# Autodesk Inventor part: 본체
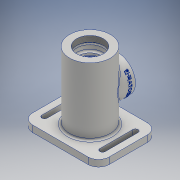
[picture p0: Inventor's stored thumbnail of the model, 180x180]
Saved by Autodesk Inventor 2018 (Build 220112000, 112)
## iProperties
Created: 2021-07
Part Number: 본체
Material: 알루미늄 6061
Document SubType Name: Modeling
Designer: 1class9
Density: 2.7 g/cm^3
Appearance: 알루미늄 - 평지
Mass: 736.573 g
Surface Area: 646.785 cm^2
Volume: 272.805 cm^3
Author: 1class9
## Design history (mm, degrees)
sketch "스케치1"
  geometry: C1 r 31 at (0, 0); 1 further point
  constraints: 1 centre point, 1 coincident
  dimensions: "d0" = 62 diameter of C1
extrude "돌출1" new body sketch "스케치1" stored distance "d1" = 102; taper "d2" = 0 deg
sketch "스케치3"
  geometry: L1 (31, -51)-(-31, -51) reference; L2 (-31, -51)-(-31, 51) reference; L3 (-31, 51)-(31, 51) reference; L4 (31, 51)-(31, -51) reference; L5 (42, -5)-(0, -5); L6 (0, -5)-(0, -32); L7 (0, -32)-(42, -32); L8 (42, -32)-(42, -5); 2 further points
  constraints: 8 end point, 2 parallel, 1 horizontal, 1 midpoint, 1 perpendicular, 1 vertical alignment
  dimensions: "d4" = 46 distance between parallel lines of L5 L1; "d5" = 54 diameter of L7 L5; "d6" = 42 distance between parallel lines of L6 L8
revolve "회전1" sketch "스케치3" stored, may be unused: angle "d7" = 90 deg
sketch "스케치4"
  geometry: L1 (-58, -45)-(58, -45); L2 (58, -45)-(58, 45); L3 (58, 45)-(-58, 45); L4 (-58, 45)-(-58, -45); L5 (-58, -45)-(58, 45); L6 (58, -45)-(-58, 45); 1 further point
  constraints: 12 end point, 2 midpoint, 2 parallel, 1 horizontal, 1 perpendicular
  dimensions: "d8" = 116 distance of L2.end L3.end; "d9" = 90 distance of L1.end L2.end
extrude "돌출2" join sketch "스케치4" distance "d10" = 10; taper "d11" = 0 deg
sketch "스케치5"
  geometry: C1 r 35 at (0, 0); 1 further point
  constraints: 1 centre point, 1 coincident
  dimensions: "d12" = 70 diameter of C1
extrude "돌출3" join sketch "스케치5" distance "d13" = 3; taper "d14" = 0 deg
hole "구멍1" diameter "d17" = 40.376; stored, may be unused: countersink angle "d21" = 90 deg, drill point angle "d23" = 118 deg; dims "d15" = 10, "d16" = 10, "d18" = 84, "d19" = 4, "d20" = 2, "d22" = 9
sketch "스케치8"
  geometry: L1 (20.188, 42)-(-20.188, 42) reference; L2 (20.188, 42)-(-20.188, 42) reference; L3 (0, 42)-(24, 42); L4 (24, 42)-(24, 39); L5 (24, 39)-(0, 39); L6 (0, 39)-(0, 42); L7 (0, 39)-(20, 39); L8 (20, 39)-(20, 33); L9 (0, 30)-(0, 39); L10 (0, 30)-(17, 30); L11 (-35, -64)-(35, -64) reference; A1 r 3 centre (17, 33) between (17, 30) and (20, 33); 2 further points
  constraints: 16 end point, 3 horizontal, 3 parallel, 2 perpendicular, 2 point on circle, 2 point on line, 2 tangent, 1 centre point, 1 midpoint
  dimensions: "d24" = 48 diameter of L4 L6; "d25" = 3 distance of L3.end L4.end; "d26" = 9 distance of point (20, 30) L7.end; "d27" = 40 diameter of L8 L9; "d56" = 3 radius of A1 (derived)
revolve "회전2" sketch "스케치8" stored, may be unused: angle "d33" = 90 deg
sketch "스케치9"
  geometry: L1 (42, 22)-(42, -32) reference; L2 (42, -5)-(109.389, -5); L3 (0, 25)-(17.5, 25); L4 (17.5, 25)-(17.5, -35); L5 (17.5, -35)-(0, -35); L6 (0, -8.476)-(17.5, -35); L7 (17.5, 25)-(0, -8.476); L8 (0, 25)-(0, -35); 3 further points
  constraints: 14 end point, 3 point on line, 2 horizontal, 2 midpoint, 2 vertical alignment, 1 horizontal alignment, 1 parallel, 1 perpendicular
  dimensions: "d34" = 60 distance of L3.end L4.end; "d35" = 35 diameter of L4 L8
revolve "회전3" sketch "스케치9" stored, may be unused: angle "d36" = 90 deg
sketch "스케치10"
  geometry: L1 (31, 22)-(42, 22) reference; L2 (42, 22)-(42, -32) reference; L3 (42, -32)-(31, -32) reference; L4 (31, -32)-(31, -51) reference; L5 (31, -51)-(45, -51) reference; L6 (45, -51)-(45, -61) reference; L7 (45, -61)-(35, -61) reference; L8 (35, -61)-(35, -64) reference; L9 (35, -64)-(-35, -64) reference; L10 (-35, -64)-(-35, -61) reference; L11 (-35, -61)-(-45, -61) reference; L12 (-45, -61)-(-45, -51) reference; L13 (-45, -51)-(-31, -51) reference; L14 (-31, -51)-(-31, 51) reference; L15 (-31, 51)-(-20.188, 51) reference; L16 (-20.188, 51)-(-20.188, 42) reference; L17 (-20.188, 42)-(-24, 42) reference; L18 (-24, 42)-(-24, 39) reference; L19 (-24, 39)-(-20, 39) reference; L20 (-20, 39)-(-20, 33) reference; L21 (-17, 30)-(-0.217, 30) reference; L22 (-0.217, 30)-(0, 29.87) reference; L23 (0, 29.87)-(0.217, 30) reference; L24 (0.217, 30)-(17, 30) reference; L25 (20, 33)-(20, 39) reference; L26 (20, 39)-(24, 39) reference; L27 (24, 39)-(24, 42) reference; L28 (24, 42)-(20.188, 42) reference; L29 (20.188, 42)-(20.188, 51) reference; L30 (20.188, 51)-(31, 51) reference; L31 (31, 51)-(31, 22) reference; L32 (-17.5, -35)-(17.5, -35) reference; L33 (17.5, -35)-(17.5, 25) reference; L34 (17.5, 25)-(-17.5, 25) reference; L35 (-17.5, 25)-(-17.5, -35) reference; L36 (17.5, 25)-(-17.5, 25) reference; L37 (0, 25)-(18.5, 25); L38 (18.5, 25)-(18.5, 26.75); L39 (18.5, 26.75)-(0, 26.75); L40 (0, 26.75)-(0, 25); A1 r 3 centre (-17, 33) between (-20, 33) and (-17, 30) reference; A2 r 3 centre (17, 33) between (17, 30) and (20, 33) reference; 1 further point
  constraints: 8 end point, 2 parallel, 1 horizontal, 1 midpoint, 1 perpendicular
  dimensions: "d37" = 1.75 distance of L37.end L38.end; "d38" = 37 diameter of L38 L40
revolve "회전4" sketch "스케치10" stored, may be unused: angle "d39" = 90 deg
sketch "스케치11"
  geometry: L1 (20, 39)-(-20, 39) reference; L2 (17.5, 25)-(-17.5, 25) reference; L3 (17.5, -35)-(-17.5, -35) reference; L4 (18.5, 26.75)-(-18.5, 26.75) reference; L5 (0, 29.87)-(-0.217, 30) reference; L6 (-0.108, 29.935)-(17.392, 29.935); L7 (17.392, 29.935)-(17.392, 26.75); L8 (17.392, 26.75)-(-0.108, 26.75); L9 (-0.108, 26.75)-(-0.108, 29.935); 3 further points
  constraints: 8 end point, 2 parallel, 1 horizontal, 1 midpoint, 1 perpendicular, 1 point on line
  dimensions: "d40" = 35 diameter of L7 L9
revolve "회전5" sketch "스케치11" stored, may be unused: angle "d41" = 90 deg
sketch "스케치12"
  geometry: L1 (-17.5, -35)-(17.5, -35) reference; L2 (17.5, -35)-(17.5, 25) reference; L3 (17.5, 25)-(18.5, 25) reference; L4 (18.5, 25)-(18.5, 26.75) reference; L5 (18.5, 26.75)-(17.392, 26.75) reference; L6 (17.392, 26.75)-(17.392, 29.935) reference; L7 (17.392, 29.935)-(0.108, 29.935) reference; L8 (0.108, 29.935)-(0.217, 30) reference; L9 (0.217, 30)-(17, 30) reference; L10 (20, 33)-(20, 39) reference; L11 (20, 39)-(24, 39) reference; L12 (24, 39)-(24, 42) reference; L13 (24, 42)-(20.188, 42) reference; L14 (20.188, 42)-(20.188, 51) reference; L15 (20.188, 51)-(31, 51) reference; L16 (31, 51)-(31, 22) reference; L17 (31, 22)-(42, 22) reference; L18 (42, 22)-(42, -32) reference; L19 (42, -32)-(31, -32) reference; L20 (31, -32)-(31, -51) reference; L21 (31, -51)-(45, -51) reference; L22 (45, -51)-(45, -61) reference; L23 (45, -61)-(35, -61) reference; L24 (35, -61)-(35, -64) reference; L25 (35, -64)-(-35, -64) reference; L26 (-35, -64)-(-35, -61) reference; L27 (-35, -61)-(-45, -61) reference; L28 (-45, -61)-(-45, -51) reference; L29 (-45, -51)-(-31, -51) reference; L30 (-31, -51)-(-31, 51) reference; L31 (-31, 51)-(-20.188, 51) reference; L32 (-20.188, 51)-(-20.188, 42) reference; L33 (-20.188, 42)-(-24, 42) reference; L34 (-24, 42)-(-24, 39) reference; L35 (-24, 39)-(-20, 39) reference; L36 (-20, 39)-(-20, 33) reference; L37 (-17, 30)-(-0.217, 30) reference; L38 (-0.217, 30)-(-0.108, 29.935) reference; L39 (-0.108, 29.935)-(-17.608, 29.935) reference; L40 (-17.608, 29.935)-(-17.608, 26.75) reference; L41 (-17.608, 26.75)-(-18.5, 26.75) reference; L42 (-18.5, 26.75)-(-18.5, 25) reference; L43 (-18.5, 25)-(-17.5, 25) reference; L44 (-17.5, 25)-(-17.5, -35) reference; L45 (0, -35)-(16, -35); L46 (16, -35)-(16, -37); L47 (13, -40)-(0, -40); L48 (0, -40)-(0, -35); L49 (0, -40)-(10, -40); L50 (10, -40)-(10, -42); L51 (10, -42)-(0, -42); L52 (0, -42)-(0, -40); L53 (0, -42)-(12.2, -42); L54 (12.5, -42.3)-(12.5, -48.6); L55 (12.5, -48.6)-(0, -48.6); L56 (0, -48.6)-(0, -42); A1 r 3 centre (17, 33) between (17, 30) and (20, 33) reference; A2 r 3 centre (-17, 33) between (-20, 33) and (-17, 30) reference; A3 r 3 centre (13, -37) between (13, -40) and (16, -37); A4 r 0.3 centre (12.2, -42.3) between (12.5, -42.3) and (12.2, -42); 3 further points
  constraints: 24 end point, 6 parallel, 4 point on circle, 4 point on line, 4 tangent, 3 horizontal, 3 perpendicular, 2 centre point, 1 midpoint
  dimensions: "d42" = 32 diameter of L46 L48; "d43" = 5 distance of L45.end point (16, -40); "d44" = 20 diameter of L50 L52; "d45" = 2 distance of L49.end L50.end; "d46" = 6.6 distance of point (12.5, -42) L54.end; "d47" = 25 diameter of L54 L56; "d67" = 3 radius of A3; "d68" = 0.3 radius of A4 (derived)
revolve "회전6" sketch "스케치12" stored, may be unused: angle "d48" = 90 deg
sketch "스케치14"
  geometry: L1 (-18.5, 26.75)-(-18.5, 25) reference; L2 (-18.5, 25)-(-17.5, 25) reference; L3 (-17.5, 25)-(-17.5, -35) reference; L4 (-17.5, -35)-(-16, -35) reference; L5 (-16, -35)-(-16, -37) reference; L6 (-13, -40)-(-10, -40) reference; L7 (-10, -40)-(-10, -42) reference; L8 (-10, -42)-(-12.2, -42) reference; L9 (-12.5, -42.3)-(-12.5, -48.6) reference; L10 (-12.5, -48.6)-(12.5, -48.6) reference; L11 (12.5, -48.6)-(12.5, -42.3) reference; L12 (12.2, -42)-(10, -42) reference; L13 (10, -42)-(10, -40) reference; L14 (10, -40)-(13, -40) reference; L15 (16, -37)-(16, -35) reference; L16 (16, -35)-(17.5, -35) reference; L17 (17.5, -35)-(17.5, 25) reference; L18 (17.5, 25)-(18.5, 25) reference; L19 (18.5, 25)-(18.5, 26.75) reference; L20 (18.5, 26.75)-(17.392, 26.75) reference; L21 (17.392, 26.75)-(17.392, 29.935) reference; L22 (17.392, 29.935)-(0.108, 29.935) reference; L23 (0.108, 29.935)-(0.217, 30) reference; L24 (0.217, 30)-(17, 30) reference; L25 (20, 33)-(20, 39) reference; L26 (20, 39)-(24, 39) reference; L27 (24, 39)-(24, 42) reference; L28 (24, 42)-(20.188, 42) reference; L29 (20.188, 42)-(20.188, 51) reference; L30 (20.188, 51)-(31, 51) reference; L31 (31, 51)-(31, 22) reference; L32 (31, 22)-(42, 22) reference; L33 (42, 22)-(42, -32) reference; L34 (42, -32)-(31, -32) reference; L35 (31, -32)-(31, -51) reference; L36 (31, -51)-(45, -51) reference; L37 (45, -51)-(45, -61) reference; L38 (45, -61)-(35, -61) reference; L39 (35, -61)-(35, -64) reference; L40 (35, -64)-(-35, -64) reference; L41 (-35, -64)-(-35, -61) reference; L42 (-35, -61)-(-45, -61) reference; L43 (-45, -61)-(-45, -51) reference; L44 (-45, -51)-(-31, -51) reference; L45 (-31, -51)-(-31, 51) reference; L46 (-31, 51)-(-20.188, 51) reference; L47 (-20.188, 51)-(-20.188, 42) reference; L48 (-20.188, 42)-(-24, 42) reference; L49 (-24, 42)-(-24, 39) reference; L50 (-24, 39)-(-20, 39) reference; L51 (-20, 39)-(-20, 33) reference; L52 (-17, 30)-(-0.217, 30) reference; L53 (-0.217, 30)-(-0.108, 29.935) reference; L54 (-0.108, 29.935)-(-17.608, 29.935) reference; L55 (-17.608, 29.935)-(-17.608, 26.75) reference; L56 (-17.608, 26.75)-(-18.5, 26.75) reference; L57 (12.5, -48.6)-(12.904, -49.3); L58 (12.904, -49.3)-(0, -49.3); L59 (-12.5, -48.6)-(12.5, -48.6) reference; L60 (0, -48.6)-(0, -49.3); L61 (12.5, -48.6)-(0, -48.6); A1 r 3 centre (17, 33) between (17, 30) and (20, 33) reference; A2 r 3 centre (-17, 33) between (-20, 33) and (-17, 30) reference; A3 r 3 centre (-13, -37) between (-16, -37) and (-13, -40) reference; A4 r 0.3 centre (-12.2, -42.3) between (-12.2, -42) and (-12.5, -42.3) reference; A5 r 0.3 centre (12.2, -42.3) between (12.5, -42.3) and (12.2, -42) reference; A6 r 3 centre (13, -37) between (13, -40) and (16, -37) reference; 1 further point
  constraints: 8 end point, 2 horizontal, 1 midpoint, 1 vertical
  dimensions: "d49" = 30 deg angle of L11 L57; "d50" = 0.7 distance between parallel lines of L61 L58
revolve "회전7" sketch "스케치14" stored, may be unused: angle "d51" = 90 deg
sketch "스케치15"
  geometry: L1 (-18.5, 26.75)-(-18.5, 25) reference; L2 (-18.5, 25)-(-17.5, 25) reference; L3 (-17.5, 25)-(-17.5, -35) reference; L4 (-17.5, -35)-(-16, -35) reference; L5 (-16, -35)-(-16, -37) reference; L6 (-13, -40)-(-10, -40) reference; L7 (-10, -40)-(-10, -42) reference; L8 (-10, -42)-(-12.2, -42) reference; L9 (-12.5, -42.3)-(-12.5, -48.6) reference; L10 (-12.5, -48.6)-(-12.904, -49.3) reference; L11 (-12.904, -49.3)-(12.904, -49.3) reference; L12 (12.904, -49.3)-(12.5, -48.6) reference; L13 (12.5, -48.6)-(12.5, -42.3) reference; L14 (12.2, -42)-(10, -42) reference; L15 (10, -42)-(10, -40) reference; L16 (10, -40)-(13, -40) reference; L17 (16, -37)-(16, -35) reference; L18 (16, -35)-(17.5, -35) reference; L19 (17.5, -35)-(17.5, 25) reference; L20 (17.5, 25)-(18.5, 25) reference; L21 (18.5, 25)-(18.5, 26.75) reference; L22 (18.5, 26.75)-(17.392, 26.75) reference; L23 (17.392, 26.75)-(17.392, 29.935) reference; L24 (17.392, 29.935)-(0.108, 29.935) reference; L25 (0.108, 29.935)-(0.217, 30) reference; L26 (0.217, 30)-(17, 30) reference; L27 (20, 33)-(20, 39) reference; L28 (20, 39)-(24, 39) reference; L29 (24, 39)-(24, 42) reference; L30 (24, 42)-(20.188, 42) reference; L31 (20.188, 42)-(20.188, 51) reference; L32 (20.188, 51)-(31, 51) reference; L33 (31, 51)-(31, 22) reference; L34 (31, 22)-(42, 22) reference; L35 (42, 22)-(42, -32) reference; L36 (42, -32)-(31, -32) reference; L37 (31, -32)-(31, -51) reference; L38 (31, -51)-(45, -51) reference; L39 (45, -51)-(45, -61) reference; L40 (45, -61)-(35, -61) reference; L41 (35, -61)-(35, -64) reference; L42 (35, -64)-(-35, -64) reference; L43 (-35, -64)-(-35, -61) reference; L44 (-35, -61)-(-45, -61) reference; L45 (-45, -61)-(-45, -51) reference; L46 (-45, -51)-(-31, -51) reference; L47 (-31, -51)-(-31, 51) reference; L48 (-31, 51)-(-20.188, 51) reference; L49 (-20.188, 51)-(-20.188, 42) reference; L50 (-20.188, 42)-(-24, 42) reference; L51 (-24, 42)-(-24, 39) reference; L52 (-24, 39)-(-20, 39) reference; L53 (-20, 39)-(-20, 33) reference; L54 (-17, 30)-(-0.217, 30) reference; L55 (-0.217, 30)-(-0.108, 29.935) reference; L56 (-0.108, 29.935)-(-17.608, 29.935) reference; L57 (-17.608, 29.935)-(-17.608, 26.75) reference; L58 (-17.608, 26.75)-(-18.5, 26.75) reference; L59 (12.904, -49.3)-(-12.904, -49.3) reference; L60 (0, -49.3)-(13.984, -49.3); L61 (16.762, -51.166)-(22, -64); L62 (-35, -64)-(35, -64) reference; L63 (0, -49.3)-(0, -64); L64 (22, -64)-(0, -64); A1 r 3 centre (13.984, -52.3) between (16.762, -51.166) and (13.984, -49.3); A2 r 3 centre (17, 33) between (17, 30) and (20, 33) reference; A3 r 3 centre (-17, 33) between (-20, 33) and (-17, 30) reference; A4 r 3 centre (-13, -37) between (-16, -37) and (-13, -40) reference; A5 r 0.3 centre (-12.2, -42.3) between (-12.2, -42) and (-12.5, -42.3) reference; A6 r 0.3 centre (12.2, -42.3) between (12.5, -42.3) and (12.2, -42) reference; A7 r 3 centre (13, -37) between (13, -40) and (16, -37) reference; 2 further points
  constraints: 8 end point, 4 point on line, 2 midpoint, 2 point on circle, 2 tangent, 1 centre point, 1 collinear
  dimensions: "d52" = 32 diameter of point (16, -49.3) L63; "d53" = 44 diameter of L61.end L63; "d54" = 3 radius of A1
revolve "회전8" sketch "스케치15" stored, may be unused: angle "d55" = 90 deg
sketch "스케치16"
  geometry: L1 (17.392, 29.935)-(17.392, 26.75) reference; L2 (-0.108, 31.531)-(17.392, 31.531); L3 (17.392, 31.531)-(17.392, 29.003); L4 (17.392, 29.003)-(-0.108, 29.003); L5 (-0.108, 29.003)-(-0.108, 31.531); L6 (18.5, 25)-(18.5, 26.75) reference; L7 (18.5, 26.75)-(17.392, 26.75) reference; L8 (17.392, 26.75)-(17.392, 29.935) reference; L9 (17.392, 29.935)-(0.108, 29.935) reference; L10 (0.108, 29.935)-(0.217, 30) reference; L11 (0.217, 30)-(17, 30) reference; L12 (20, 33)-(20, 39) reference; L13 (20, 39)-(24, 39) reference; L14 (24, 39)-(24, 42) reference; L15 (24, 42)-(20.188, 42) reference; L16 (20.188, 42)-(20.188, 51) reference; L17 (20.188, 51)-(31, 51) reference; L18 (31, 51)-(31, 22) reference; L19 (31, 22)-(42, 22) reference; L20 (42, 22)-(42, -32) reference; L21 (42, -32)-(31, -32) reference; L22 (31, -32)-(31, -51) reference; L23 (31, -51)-(45, -51) reference; L24 (45, -51)-(45, -61) reference; L25 (45, -61)-(35, -61) reference; L26 (35, -61)-(35, -64) reference; L27 (35, -64)-(22, -64) reference; L28 (22, -64)-(16.762, -51.166) reference; L29 (13.984, -49.3)-(12.904, -49.3) reference; L30 (12.904, -49.3)-(12.5, -48.6) reference; L31 (12.5, -48.6)-(12.5, -42.3) reference; L32 (12.2, -42)-(10, -42) reference; L33 (10, -42)-(10, -40) reference; L34 (10, -40)-(13, -40) reference; L35 (16, -37)-(16, -35) reference; L36 (16, -35)-(17.5, -35) reference; L37 (17.5, -35)-(17.5, 25) reference; L38 (17.5, 25)-(18.5, 25) reference; L39 (-18.5, 26.75)-(-18.5, 25) reference; L40 (-18.5, 25)-(-17.5, 25) reference; L41 (-17.5, 25)-(-17.5, -35) reference; L42 (-17.5, -35)-(-16, -35) reference; L43 (-16, -35)-(-16, -37) reference; L44 (-13, -40)-(-10, -40) reference; L45 (-10, -40)-(-10, -42) reference; L46 (-10, -42)-(-12.2, -42) reference; L47 (-12.5, -42.3)-(-12.5, -48.6) reference; L48 (-12.5, -48.6)-(-12.904, -49.3) reference; L49 (-12.904, -49.3)-(-13.984, -49.3) reference; L50 (-16.762, -51.166)-(-22, -64) reference; L51 (-22, -64)-(-35, -64) reference; L52 (-35, -64)-(-35, -61) reference; L53 (-35, -61)-(-45, -61) reference; L54 (-45, -61)-(-45, -51) reference; L55 (-45, -51)-(-31, -51) reference; L56 (-31, -51)-(-31, 51) reference; L57 (-31, 51)-(-20.188, 51) reference; L58 (-20.188, 51)-(-20.188, 42) reference; L59 (-20.188, 42)-(-24, 42) reference; L60 (-24, 42)-(-24, 39) reference; L61 (-24, 39)-(-20, 39) reference; L62 (-20, 39)-(-20, 33) reference; L63 (-17, 30)-(-0.217, 30) reference; L64 (-0.217, 30)-(-0.108, 29.935) reference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; A1 r 3 centre (17, 33) between (17, 30) and (20, 33) reference; A2 r 3 centre (13.984, -52.3) between (16.762, -51.166) and (13.984, -49.3) reference; A3 r 3 centre (-13.984, -52.3) between (-13.984, -49.3) and (-16.762, -51.166) reference; A4 r 3 centre (-17, 33) between (-20, 33) and (-17, 30) reference; A5 r 0.3 centre (12.2, -42.3) between (12.5, -42.3) and (12.2, -42) reference; A6 r 3 centre (13, -37) between (13, -40) and (16, -37) reference; A7 r 3 centre (-13, -37) between (-16, -37) and (-13, -40) reference; A8 r 0.3 centre (-12.2, -42.3) between (-12.2, -42) and (-12.5, -42.3) reference; 2 further points
  constraints: 8 end point, 2 parallel, 1 horizontal, 1 midpoint, 1 perpendicular, 1 point on line, 1 vertical alignment
  dimensions: "d57" = 2.52886 distance of L2.end L3.end; "d58" = 19.46862 distance between parallel lines of L17 L2
revolve "회전9" sketch "스케치16" stored, may be unused: angle "d59" = 90 deg
sketch "스케치17"
  geometry: L1 (18.5, 25)-(18.5, 26.75) reference; L2 (18.5, 26.75)-(17.392, 26.75) reference; L3 (17.392, 26.75)-(17.392, 30.026) reference; L4 (20, 33)-(20, 39) reference; L5 (20, 39)-(24, 39) reference; L6 (24, 39)-(24, 42) reference; L7 (24, 42)-(20.188, 42) reference; L8 (20.188, 42)-(20.188, 51) reference; L9 (20.188, 51)-(31, 51) reference; L10 (31, 51)-(31, 22) reference; L11 (31, 22)-(42, 22) reference; L12 (42, 22)-(42, -32) reference; L13 (42, -32)-(31, -32) reference; L14 (31, -32)-(31, -51) reference; L15 (31, -51)-(45, -51) reference; L16 (45, -51)-(45, -61) reference; L17 (45, -61)-(35, -61) reference; L18 (35, -61)-(35, -64) reference; L19 (35, -64)-(22, -64) reference; L20 (22, -64)-(16.762, -51.166) reference; L21 (13.984, -49.3)-(12.904, -49.3) reference; L22 (12.904, -49.3)-(12.5, -48.6) reference; L23 (12.5, -48.6)-(12.5, -42.3) reference; L24 (12.2, -42)-(10, -42) reference; L25 (10, -42)-(10, -40) reference; L26 (10, -40)-(13, -40) reference; L27 (16, -37)-(16, -35) reference; L28 (16, -35)-(17.5, -35) reference; L29 (17.5, -35)-(17.5, 25) reference; L30 (17.5, 25)-(18.5, 25) reference; L31 (-18.5, 26.75)-(-18.5, 25) reference; L32 (-18.5, 25)-(-17.5, 25) reference; L33 (-17.5, 25)-(-17.5, -35) reference; L34 (-17.5, -35)-(-16, -35) reference; L35 (-16, -35)-(-16, -37) reference; L36 (-13, -40)-(-10, -40) reference; L37 (-10, -40)-(-10, -42) reference; L38 (-10, -42)-(-12.2, -42) reference; L39 (-12.5, -42.3)-(-12.5, -48.6) reference; L40 (-12.5, -48.6)-(-12.904, -49.3) reference; L41 (-12.904, -49.3)-(-13.984, -49.3) reference; L42 (-16.762, -51.166)-(-22, -64) reference; L43 (-22, -64)-(-35, -64) reference; L44 (-35, -64)-(-35, -61) reference; L45 (-35, -61)-(-45, -61) reference; L46 (-45, -61)-(-45, -51) reference; L47 (-45, -51)-(-31, -51) reference; L48 (-31, -51)-(-31, 51) reference; L49 (-31, 51)-(-20.188, 51) reference; L50 (-20.188, 51)-(-20.188, 42) reference; L51 (-20.188, 42)-(-24, 42) reference; L52 (-24, 42)-(-24, 39) reference; L53 (-24, 39)-(-20, 39) reference; L54 (-20, 39)-(-20, 33) reference; L55 (-17.608, 30.062)-(-17.608, 26.75) reference; L56 (-17.608, 26.75)-(-18.5, 26.75) reference; L57 (0, 14)-(23, 14); L58 (26, 11)-(26, -21); L59 (23, -24)-(0, -24); L60 (0, -24)-(0, 14); L61 (42, 22)-(42, -32) reference; L62 (42, -5)-(71.492, -5); A1 r 3 centre (17, 33) between (17.392, 30.026) and (20, 33) reference; A2 r 3 centre (13.984, -52.3) between (16.762, -51.166) and (13.984, -49.3) reference; A3 r 3 centre (-13.984, -52.3) between (-13.984, -49.3) and (-16.762, -51.166) reference; A4 r 3 centre (-17, 33) between (-20, 33) and (-17.608, 30.062) reference; A5 r 3 centre (23, 11) between (26, 11) and (23, 14); A6 r 3 centre (23, -21) between (23, -24) and (26, -21); A7 r 0.3 centre (12.2, -42.3) between (12.5, -42.3) and (12.2, -42) reference; A8 r 3 centre (13, -37) between (13, -40) and (16, -37) reference; A9 r 3 centre (-13, -37) between (-16, -37) and (-13, -40) reference; A10 r 0.3 centre (-12.2, -42.3) between (-12.2, -42) and (-12.5, -42.3) reference; 6 further points
  constraints: 10 end point, 4 midpoint, 4 point on circle, 4 point on line, 4 tangent, 2 centre point, 2 horizontal, 2 parallel, 1 equal radius, 1 horizontal alignment, 1 perpendicular, 1 vertical alignment
  dimensions: "d60" = 38 distance of point (26, 14) point (26, -24); "d61" = 52 diameter of L58 L60; "d62" = 3 radius of A5 (derived)
revolve "회전10" sketch "스케치17" stored, may be unused: angle "d63" = 90 deg
chamfer "모따기1" distance "d64" = 1; stored, may be unused: second distance "d65" = 2, angle "d66" = 45 deg
sketch "스케치18"
  geometry: C1 r 27 at (0, 0) reference; C2 r 16 at (0, 0); 1 further point
  constraints: 1 centre point, 1 coincident
  dimensions: "d70" = 32 diameter of C2
extrude "돌출4" cut sketch "스케치18" distance "d71" = 43.25; taper "d72" = 0 deg
chamfer "모따기2" distance "d73" = 1; stored, may be unused: second distance "d74" = 2, angle "d75" = 45 deg
fillet "모깎기1" dims "d76" = 3
node "작업 평면1"
sketch "스케치19"
  geometry: L1 (21, 27)-(21, -27) reference; 3 further points
  constraints: 1 horizontal alignment, 1 midpoint, 1 other
  dimensions: "d77" = 8 distance from line of L1 point (13, 0)
feature "엠보싱1" sketch "스케치19" dims "d10" = 10, "d11" = 0, "d78" = 0.5, "d79" = 0
sketch "스케치20"
  geometry: L1 (44, 25)-(44, -25); L2 (40, 25)-(40, -25); L3 (48, -25)-(48, 25); L4 (0, 0)-(0, -65.673); L5 (-44, 25)-(-44, -25); L6 (-40, 25)-(-40, -25); L7 (-48, -25)-(-48, 25); A1 r 4 centre (44, 25) between (48, 25) and (40, 25); A2 r 4 centre (44, -25) between (40, -25) and (48, -25); A3 r 4 centre (-44, 25) between (-40, 25) and (-48, 25); A4 r 4 centre (-44, -25) between (-48, -25) and (-40, -25); 2 further points
  constraints: 18 end point, 8 point on circle, 7 symmetric about line, 4 centre point, 4 tangent, 2 vertical, 1 horizontal alignment, 1 midpoint, 1 parallel, 2 other
  dimensions: "d80" = 4 radius of A1; "d81" = 50 distance of L1.start L1.end; "d82" = 44 distance from line of L1 L4.start
extrude "돌출5" cut sketch "스케치20" distance "d83" = 14.25; taper "d84" = 0 deg
sketch "스케치21"
  geometry: L1 (58, 46)-(-58, 46) reference; L2 (-58, 46)-(-58, 56) reference; L3 (-58, 56)-(58, 56) reference; L4 (58, 56)-(58, 46) reference; C1 r 27 at (0, 0) reference; C2 r 17 at (0, 0) reference; A1 r 22 centre (0, 0) between (-22, 0) and (22, 0); 1 further point
  constraints: 2 point on circle, 1 centre point, 1 coincident
  dimensions: "d85" = 44 diameter of A1
hole "구멍2" sketch "스케치21" at (-22, 0), (22, 0) diameter "d86" = 2.459; stored, may be unused: countersink angle "d90" = 90 deg, drill point angle "d92" = 118 deg; dims "d87" = 6, "d88" = 4, "d89" = 2, "d91" = 8
fillet "모깎기2" dims "d93" = 16
fillet "모깎기5" dims "d96" = 0.3
node "솔리드1"
node "투영된 루프1"
node "투영된 루프2"
node "투영된 루프3"
node "투영된 루프4"
node "절단 모서리 투영1"
node "절단 모서리 투영3"
node "절단 모서리 투영4"
node "절단 모서리 투영6"
node "절단 모서리 투영7"
node "절단 모서리 투영8"
node "절단 모서리 투영9"
node "절단 모서리 투영10"
